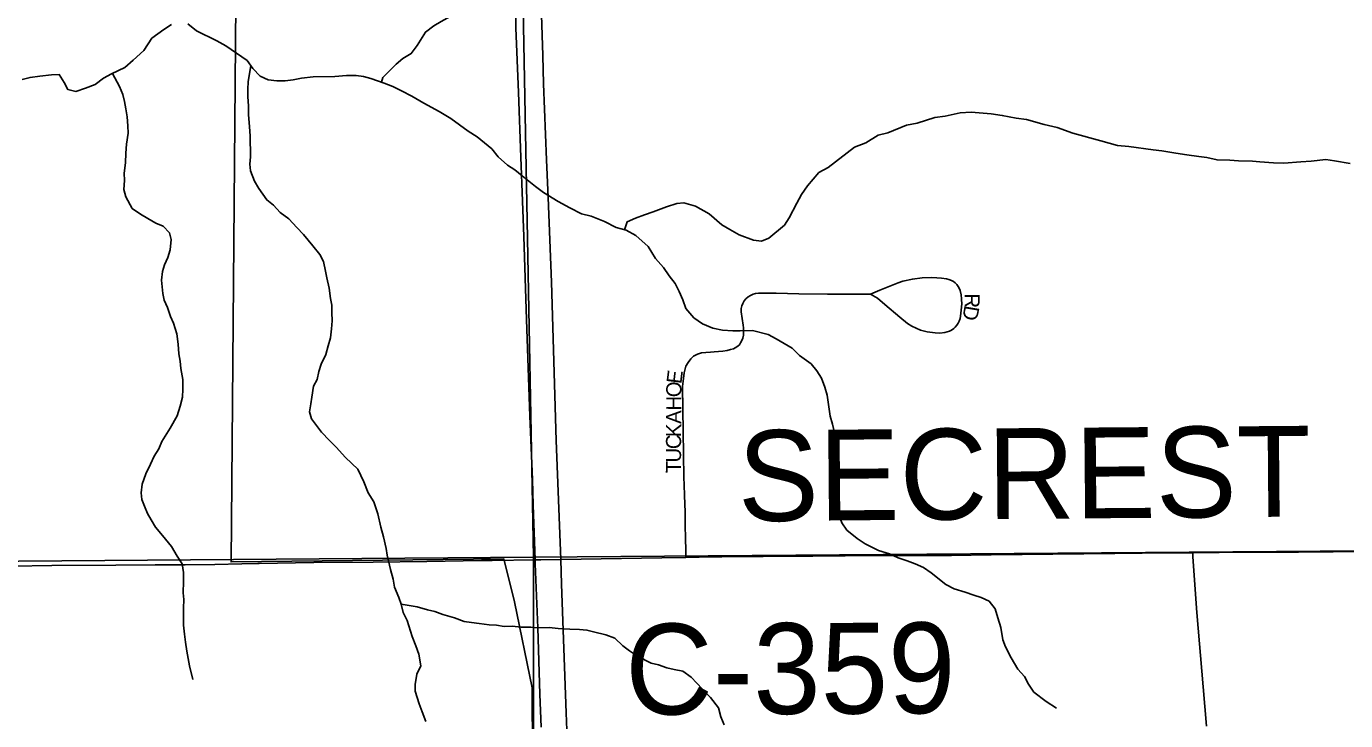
# Model space of a CAD drawing. Extents: x 1985906 to 2360102, y 891258 to 1222054.
# Drawn here: x 2128971 to 2133334, y 1014269 to 1016563 of the extents above; entities that cross this region are included whole.
import ezdxf

# ---------------------------------------------------------------- set-up
doc = ezdxf.new("R2010")
doc.units = 0
for name, color, linetype in [('GM_X_City_Street', 7, 'Continuous'), ('GM_X_Corporation', 7, 'Continuous'), ('GM_X_County_Road', 7, 'Continuous'), ('GM_X_County_Road_Text', 7, 'Continuous'), ('GM_X_Minor_River', 7, 'Continuous'), ('GM_X_Section', 7, 'Continuous'), ('GM_X_Township_Road', 7, 'Continuous'), ('GM_X_Township_Subdivision', 7, 'Continuous'), ('GM_X_Township_Subdivision_Text', 7, 'Continuous'), ('GM_X_US_Route', 7, 'Continuous')]:
    doc.layers.add(name, color=color, linetype=linetype)

msp = doc.modelspace()

# ---------------------------------------------------------------- linework, layer by layer
at = {"layer": 'GM_X_City_Street'}
msp.add_lwpolyline([(2128813.1, 1014778.2), (2128923.3, 1014779.7), (2129054.7, 1014781.3), (2129266.2, 1014783.1), (2129397.2, 1014783.8), (2129495.6, 1014784.2), (2129593.8, 1014784.9), (2129683.8, 1014786.7)], dxfattribs=at)
at = {"layer": 'GM_X_Corporation'}
msp.add_lwpolyline([(2129663.7, 1016638.8), (2129647.7, 1014793.7), (2130550, 1014803.2), (2130585.3, 1014661.5), (2130643.1, 1014377.4), (2130645.8, 1013927.4), (2130636.7, 1013870.1), (2130637.7, 1013720.1), (2130677.7, 1013567.2), (2130448.1, 1009980.8)], dxfattribs=at)
at = {"layer": 'GM_X_County_Road'}
for points in [[(2131151.7, 1014808.5), (2131195.8, 1014808.9), (2131270.8, 1014809.8), (2131367.2, 1014810.9), (2131407.8, 1014811.4), (2131473.5, 1014811.9), (2131510.5, 1014812.4), (2131571.4, 1014812.9), (2131620.4, 1014813.3), (2131678.7, 1014813.7), (2131733.5, 1014814.1), (2131785.6, 1014814.5), (2131866.9, 1014814.7), (2132030.3, 1014815), (2132161.7, 1014817), (2132570.8, 1014821.4), (2132751.2, 1014823.1), (2132827.9, 1014823.7)], [(2132827.9, 1014823.7), (2132915.4, 1014824.8), (2133178, 1014825.5), (2133407.8, 1014827.6), (2133736.1, 1014829.7), (2133998.6, 1014831.4), (2134230, 1014832.7), (2134392, 1014833.7), (2134533.6, 1014833.6)], [(2129683.8, 1014786.7), (2129736.5, 1014787.8)], [(2129736.5, 1014787.8), (2129740.7, 1014787.8), (2129922, 1014791.4), (2130117.8, 1014793.1), (2130295.5, 1014795), (2130475.5, 1014797.9), (2130511.6, 1014798.2)], [(2130511.6, 1014798.2), (2130653, 1014799.9), (2130672.2, 1014800.1), (2130738.1, 1014801.2), (2131072.4, 1014807.1)], [(2131072.4, 1014807.1), (2131151.7, 1014808.5)]]:
    msp.add_lwpolyline(points, dxfattribs=at)
at = {"layer": 'GM_X_Minor_River'}
for points in [[(2130144.9, 1016379.6), (2130150.1, 1016394.3), (2130193.7, 1016439), (2130215.5, 1016457.4), (2130243.4, 1016473.8), (2130263.2, 1016500.2), (2130290.7, 1016544.6), (2130318.5, 1016565.1), (2130342.5, 1016579.4), (2130420.2, 1016622.6), (2130454.1, 1016643.1), (2130477.9, 1016663.5), (2130503.8, 1016677.8), (2130535.6, 1016704.3), (2130569.4, 1016730.9), (2130597.2, 1016753.3), (2130648.9, 1016794.1), (2130672.8, 1016814.5), (2130712.7, 1016831), (2130734.7, 1016835.4), (2130764.8, 1016839.8), (2130786.7, 1016852.1), (2130824.2, 1016860.5)], [(2128957.3, 1016388.5), (2128983.3, 1016394.8), (2129015.4, 1016399.3), (2129053.5, 1016403.8), (2129079.6, 1016404.1), (2129096, 1016378.3), (2129108.4, 1016354.4), (2129134.5, 1016348.7), (2129166.5, 1016359.2), (2129198.5, 1016371.6), (2129226.4, 1016392.1), (2129252.3, 1016406.4), (2129296.2, 1016427.1), (2129324, 1016451.5), (2129359.7, 1016484.1), (2129385.3, 1016524.5), (2129425.1, 1016553.2), (2129451, 1016569.5)], [(2129505.2, 1016572.3), (2129533.6, 1016548.6), (2129600.3, 1016515.4), (2129630.6, 1016499.7), (2129701.5, 1016450.5), (2129719.9, 1016424.7), (2129744.4, 1016399), (2129770.6, 1016387.3), (2129798.8, 1016383.6), (2129826.9, 1016384)], [(2129712.9, 1016434.5), (2129704.4, 1016380.4), (2129702.7, 1016356.3), (2129703.1, 1016332.2), (2129705.5, 1016300.2), (2129705.8, 1016272.1), (2129708.4, 1016232), (2129710.8, 1016202), (2129711.7, 1016131.8), (2129710, 1016107.7), (2129712.3, 1016085.7), (2129724.8, 1016051.7), (2129739.1, 1016027.8), (2129765.7, 1015990.1), (2129788.1, 1015972.3), (2129810.5, 1015948.6), (2129838.8, 1015926.9), (2129865.3, 1015899.2), (2129887.7, 1015875.4), (2129918.3, 1015837.7), (2129940.8, 1015809.9), (2129953.1, 1015786), (2129959.6, 1015754), (2129963.9, 1015732), (2129972.4, 1015698), (2129976.8, 1015664), (2129981.1, 1015642), (2129981.4, 1015617.9), (2129981.8, 1015589.8), (2129980.1, 1015563.7), (2129976.5, 1015533.6), (2129968.8, 1015507.4), (2129961.1, 1015479.2), (2129945.5, 1015446.9), (2129937.8, 1015422.8), (2129932.1, 1015396.6), (2129920.3, 1015374.4), (2129914.8, 1015338.2), (2129911, 1015316.1), (2129907.4, 1015290), (2129913.7, 1015266), (2129946.4, 1015222.3), (2129972.9, 1015194.6), (2129995.2, 1015172.8), (2130025.8, 1015139.1), (2130066.5, 1015099.6), (2130087.1, 1015057.7), (2130101.6, 1015021.8), (2130120.1, 1014992), (2130132.6, 1014952), (2130143.3, 1014908.1), (2130151.7, 1014876.1), (2130160.2, 1014838.1), (2130164.5, 1014816.1), (2130175.2, 1014768.1), (2130183.6, 1014736.1), (2130188, 1014710.1), (2130202.5, 1014676.2), (2130210.8, 1014654.2), (2130217.2, 1014626.2), (2130229.6, 1014600.3), (2130246.4, 1014546.4), (2130258.8, 1014516.5), (2130269.2, 1014488.5), (2130275.7, 1014450.5), (2130262, 1014422.3), (2130256.4, 1014388.1), (2130256.7, 1014366), (2130269.3, 1014324.1), (2130279.7, 1014298.1), (2130292.2, 1014266.2)], [(2129255.3, 1016407.9), (2129278.9, 1016364.7), (2129289.3, 1016338.8), (2129295.6, 1016314.8), (2129300, 1016290.8), (2129304.3, 1016264.7), (2129306.7, 1016234.7), (2129307, 1016210.6), (2129301.5, 1016174.4), (2129299.8, 1016144.3), (2129298.3, 1016112.2), (2129294.7, 1016078.1), (2129295, 1016054), (2129293.4, 1016023.9), (2129299.7, 1015999.9), (2129320.3, 1015962.1), (2129348.7, 1015942.4), (2129372.9, 1015928.7), (2129399.2, 1015913), (2129423.5, 1015903.3), (2129443.8, 1015881.5), (2129450.1, 1015859.5), (2129446.6, 1015825.4), (2129438.9, 1015799.2), (2129427.1, 1015775), (2129421.4, 1015752.8), (2129417.8, 1015724.7), (2129422.3, 1015680.7), (2129426.6, 1015658.7), (2129437, 1015634.7), (2129447.4, 1015604.8), (2129457.8, 1015582.8), (2129468.3, 1015546.9), (2129472.7, 1015512.9), (2129475.1, 1015480.8), (2129479.5, 1015456.8), (2129481.8, 1015432.8), (2129488.3, 1015396.7), (2129488.7, 1015364.7), (2129487, 1015338.5), (2129479.4, 1015308.4), (2129469.8, 1015276.1), (2129446.2, 1015235.7), (2129418.7, 1015191.2), (2129408.9, 1015167), (2129393.2, 1015142.8), (2129381.5, 1015116.5), (2129365.8, 1015084.2), (2129354.2, 1015050), (2129350.6, 1015021.8), (2129352.9, 1014999.8), (2129361.2, 1014977.9), (2129371.5, 1014953.9), (2129383.9, 1014932), (2129398.2, 1014908.2), (2129420.7, 1014880.4), (2129451.3, 1014844.7), (2129469.8, 1014812.8), (2129486.2, 1014787), (2129490.5, 1014759), (2129490.9, 1014728.9), (2129489.4, 1014690.8), (2129491.7, 1014668.7), (2129490.1, 1014640.6), (2129490.8, 1014584.5), (2129493.2, 1014554.4), (2129497.5, 1014528.4), (2129501.9, 1014498.4), (2129510.6, 1014450.3), (2129521.2, 1014404.4)], [(2129826.9, 1016384), (2129853, 1016386.4), (2129881, 1016392.8), (2129919.1, 1016397.3), (2129991.4, 1016398.2), (2130029.5, 1016400.8), (2130061.6, 1016401.2), (2130085.8, 1016397.5), (2130109.9, 1016391.8), (2130154.3, 1016376.3), (2130182.6, 1016364.7), (2130210.9, 1016351), (2130245.2, 1016333.4), (2130285.7, 1016309.9), (2130336.3, 1016282.5), (2130374.7, 1016258.9), (2130431.5, 1016217.6), (2130461.9, 1016197.9), (2130510.6, 1016158.5), (2130531, 1016132.7), (2130561.5, 1016105), (2130585.8, 1016089.3), (2130610.1, 1016069.5), (2130654.8, 1016034), (2130681.1, 1016014.3), (2130729.7, 1015984.9), (2130768.1, 1015963.3), (2130806.5, 1015943.8), (2130838.8, 1015936.2), (2130883.2, 1015918.8), (2130921.6, 1015899.2), (2130953.9, 1015889.6), (2130986.2, 1015872), (2131026.8, 1015836.4), (2131051.5, 1015796.6), (2131077.9, 1015766.9), (2131096.4, 1015739.1), (2131116.8, 1015713.3), (2131129.2, 1015687.4), (2131141.6, 1015659.4), (2131152, 1015631.5), (2131178.5, 1015599.8), (2131206.9, 1015580.1), (2131241.2, 1015566.5), (2131273.4, 1015558.9), (2131307.6, 1015557.4), (2131331.7, 1015557.7), (2131371.8, 1015558.2), (2131424.2, 1015544.9), (2131450.5, 1015531.2), (2131503.1, 1015499.8), (2131527.5, 1015476.1), (2131566, 1015448.5), (2131584.4, 1015424.7), (2131600.8, 1015400.8), (2131611.2, 1015370.9), (2131619.6, 1015344.9), (2131628.5, 1015274.8), (2131636.9, 1015248.9), (2131647.6, 1015200.9), (2131648, 1015170.8), (2131652.7, 1015116.7), (2131651.4, 1015058.5), (2131652.4, 1014984.3), (2131656.8, 1014952.3), (2131667.2, 1014922.4), (2131683.6, 1014898.5), (2131718.1, 1014870.9), (2131744.4, 1014853.2), (2131788.9, 1014831.7), (2131825.2, 1014820.2), (2131853.5, 1014806.5), (2131883.7, 1014796.9), (2131910, 1014787.2), (2131938.2, 1014775.5), (2131962.6, 1014757.8), (2132011.3, 1014718.3), (2132039.6, 1014704.7), (2132075.9, 1014693.1), (2132104.1, 1014683.5), (2132128.3, 1014675.8), (2132154.5, 1014664.1), (2132175, 1014638.3), (2132183.4, 1014608.3), (2132193.8, 1014576.4), (2132200.4, 1014536.3), (2132208.7, 1014512.4), (2132227.3, 1014476.5), (2132249.8, 1014438.7), (2132272.2, 1014415), (2132284.6, 1014389), (2132303, 1014363.2), (2132343.6, 1014331.7), (2132378, 1014310.1)], [(2130948.7, 1015891.1), (2130957.5, 1015917.7), (2130985.5, 1015930.1), (2131015.4, 1015940.6), (2131043.4, 1015951), (2131087.4, 1015967.6), (2131121.4, 1015978.1), (2131145.5, 1015980.4), (2131183.8, 1015968.9), (2131228.3, 1015943.4), (2131270.9, 1015907.9), (2131297.2, 1015892.2), (2131327.6, 1015874.5), (2131376, 1015857.1), (2131402.1, 1015853.5), (2131426.1, 1015863.8), (2131477.8, 1015906.6), (2131493.5, 1015930.9), (2131519, 1015979.4), (2131534.7, 1016007.7), (2131554.4, 1016036), (2131592, 1016080.6), (2131621.9, 1016097.1), (2131709.4, 1016164.4), (2131747.3, 1016179), (2131787.2, 1016203.6), (2131819.2, 1016212), (2131881.1, 1016236.9), (2131917.2, 1016243.4), (2131975.2, 1016262.2), (2132009.3, 1016266.7), (2132059.3, 1016277.4), (2132095.4, 1016279.9), (2132161.8, 1016274.7), (2132198, 1016269.2), (2132244.3, 1016259.8), (2132278.5, 1016256.2), (2132336.9, 1016239), (2132379.2, 1016229.5), (2132431.7, 1016210.2), (2132524.4, 1016185.3), (2132578.8, 1016170), (2132617, 1016166.5), (2132697.5, 1016155.5), (2132725.6, 1016151.9), (2132771.9, 1016144.5), (2132808.1, 1016138.9), (2132848.4, 1016133.5), (2132874.5, 1016129.8), (2132908.8, 1016122.2), (2132951, 1016120.8), (2132979.1, 1016119.2), (2133025.3, 1016117.8), (2133049.4, 1016116.1), (2133095.6, 1016112.7), (2133129.8, 1016111.2), (2133186, 1016115.9), (2133220.1, 1016118.4), (2133268.2, 1016123), (2133296.4, 1016119.4), (2133348.7, 1016110.1)], [(2130210.8, 1014654.2), (2130263.1, 1014644.9), (2130297.4, 1014635.3), (2130321.6, 1014629.6), (2130347.8, 1014620), (2130386.1, 1014608.4), (2130418.4, 1014596.8), (2130442.5, 1014593.2), (2130468.7, 1014589.5), (2130500.9, 1014585.9), (2130525, 1014584.2), (2130551.1, 1014580.5), (2130577.2, 1014580.9), (2130607.4, 1014577.3), (2130639.5, 1014577.7), (2130661.6, 1014576), (2130699.8, 1014576.5), (2130730, 1014572.9), (2130768.1, 1014571.4), (2130800.3, 1014569.8), (2130824.4, 1014568.2), (2130846.6, 1014562.4), (2130886.9, 1014552.9), (2130917.1, 1014541.3), (2130943.6, 1014515.6), (2130965.9, 1014499.8), (2130992.2, 1014482.1), (2131036.7, 1014458.7), (2131060.9, 1014453), (2131089.1, 1014443.3), (2131113.3, 1014437.6), (2131141.5, 1014432), (2131169.8, 1014412.3), (2131206.5, 1014372.7), (2131233, 1014344.9), (2131259.5, 1014311.2), (2131267.9, 1014281.2), (2131278.3, 1014255.3)]]:
    msp.add_lwpolyline(points, dxfattribs=at)
at = {"layer": 'GM_X_Section'}
for points in [[(2130549.1, 1020075.3), (2130647.9, 1014808.7), (2125116.8, 1014766.3), (2125107.5, 1020101.4)], [(2135768, 1020137.7), (2135850.9, 1014849.1), (2130647.9, 1014808.7), (2130549.1, 1020075.3)], [(2130647.9, 1014808.7), (2135850.9, 1014849.1), (2135869.9, 1009550.1), (2130575.1, 1009477.1), (2130644.2, 1011228.6)], [(2125116.8, 1014766.3), (2130647.9, 1014808.7), (2130644.2, 1011228.6), (2130575.1, 1009477.1), (2125143.7, 1009493.4)]]:
    msp.add_lwpolyline(points, close=True, dxfattribs=at)
at = {"layer": 'GM_X_Township_Road'}
msp.add_lwpolyline([(2132873.1, 1014250.5), (2132862.4, 1014381.1), (2132841.4, 1014626.2), (2132828.8, 1014810.3), (2132827.9, 1014823.7)], dxfattribs=at)
at = {"layer": 'GM_X_Township_Subdivision'}
msp.add_lwpolyline([(2131151.7, 1014808.5), (2131151.5, 1014831.4), (2131150.7, 1014871.5), (2131150, 1014913.7), (2131149.5, 1014936.1), (2131149.1, 1014957.5), (2131147.4, 1015012.7), (2131146.3, 1015048.1), (2131145.5, 1015072.1), (2131143.9, 1015149.7), (2131142.4, 1015224.2), (2131140.9, 1015372.7), (2131143.5, 1015399.2), (2131146.1, 1015418.5), (2131151.9, 1015439.9), (2131159.2, 1015452.4), (2131168.5, 1015464.4), (2131177.4, 1015473.2), (2131190.4, 1015480.5), (2131204, 1015484.7), (2131217.5, 1015485.2), (2131233.1, 1015486.7), (2131245.1, 1015488.3), (2131259.7, 1015488.8), (2131273.8, 1015490.4), (2131288.9, 1015492.5), (2131299.8, 1015495.1), (2131309.2, 1015498.2), (2131320.1, 1015503.9), (2131328.7, 1015511.2), (2131333, 1015517.6), (2131337, 1015524.8), (2131339.8, 1015532.7), (2131342, 1015542.5), (2131342.7, 1015549.1), (2131342.9, 1015559.3), (2131342.4, 1015567.1), (2131341.1, 1015575.6), (2131334.5, 1015619.5), (2131334.8, 1015631.3), (2131337, 1015640.1), (2131340.5, 1015647.6), (2131344.9, 1015656.4), (2131350.2, 1015663.3), (2131357.4, 1015669.3), (2131365.3, 1015674), (2131374.6, 1015678.3), (2131382.5, 1015680.8), (2131391.6, 1015681.8), (2131450.2, 1015681.5), (2131525.7, 1015680), (2131620.5, 1015678.6), (2131762.2, 1015678.9), (2131792.9, 1015691.4), (2131853.5, 1015716), (2131869, 1015721.2), (2131900.8, 1015728.4), (2131933, 1015732.1), (2131965.3, 1015733.2), (2131981.3, 1015732.6), (2131997.5, 1015731.5), (2132014.1, 1015729.1), (2132021.9, 1015727), (2132029.8, 1015724), (2132037, 1015719.8), (2132042.4, 1015716.1), (2132047.8, 1015710.4), (2132052.7, 1015704.1), (2132055.7, 1015698.3), (2132058.7, 1015690.6), (2132062.3, 1015676.2), (2132063.7, 1015662.9), (2132063.8, 1015659.6), (2132064.2, 1015648), (2132063.8, 1015635), (2132060.1, 1015605.7), (2132058.7, 1015598.1), (2132055.9, 1015589.6), (2132052.4, 1015582.4), (2132048.1, 1015576), (2132042.8, 1015569.8), (2132037.6, 1015565.2), (2132030.3, 1015559.9), (2132023.4, 1015556.4), (2132015.8, 1015553.6), (2132008.1, 1015551.6), (2131992, 1015549.9), (2131975.7, 1015550.8), (2131949.8, 1015554.3), (2131928.2, 1015559.7), (2131913.3, 1015565.7), (2131898.7, 1015573), (2131885, 1015581.9), (2131859.4, 1015602.1), (2131810.3, 1015644.6), (2131785.9, 1015665), (2131762.2, 1015678.9)], dxfattribs=at)
at = {"layer": 'GM_X_US_Route'}
for points in [[(2130588.9, 1016672.2), (2130589.7, 1016558.2), (2130597.8, 1016345.2), (2130606.4, 1016131.1), (2130611.4, 1015986.1), (2130615.7, 1015868.9), (2130624.6, 1015594.2), (2130636.3, 1015275.4), (2130644.8, 1015066.3), (2130647.1, 1014981.1), (2130653, 1014799.9), (2130653.4, 1014787.3), (2130662.7, 1014575.1), (2130668.9, 1014356.3), (2130673.1, 1014247.3)], [(2130672.2, 1016670.3), (2130678.8, 1016467.3), (2130681, 1016373.8), (2130690.9, 1016122.7), (2130695.9, 1015997.7), (2130706.9, 1015718.4), (2130723.4, 1015195.1), (2130738.1, 1014801.2), (2130740.9, 1014720.4), (2130756, 1014294.6), (2130760.4, 1014179.9), (2130778.3, 1013704.9), (2130787.1, 1013442.9), (2130805.2, 1012918.7), (2130815.5, 1012607.5), (2130823.9, 1012378.3), (2130834.5, 1012067.2), (2130849.2, 1011690.6), (2130849.4, 1011682.6), (2130854.7, 1011526.8), (2130858.9, 1011412.1), (2130863.8, 1011269.9), (2130869.9, 1011088.4)]]:
    msp.add_lwpolyline(points, dxfattribs=at)

# ---------------------------------------------------------------- texts
at = {"layer": 'GM_X_County_Road_Text'}
for s, rotation, p in [('SECREST', 0.4761, (2131324.7, 1014927.8)), ('C-359', 0.2728, (2130951.7, 1014288.5))]:
    msp.add_text(s, height=300, rotation=rotation, dxfattribs=at).set_placement(p)
at = {"layer": 'GM_X_Township_Subdivision_Text'}
for s, rotation, p in [('R', 269.4171, (2132073.9, 1015681.1)), ('D', 260.4478, (2132073.7, 1015643.5)), ('O', 89.694, (2131136.8, 1015337.7)), ('E', 83.0715, (2131136.9, 1015380.1)), ('H', 89.6887, (2131136.6, 1015293.7)), ('A', 89.694, (2131136.3, 1015249.7)), ('C', 89.6843, (2131135.9, 1015166)), ('K', 89.7057, (2131136.1, 1015205.7)), ('T', 89.6994, (2131135.5, 1015086.8)), ('U', 89.694, (2131135.7, 1015122))]:
    msp.add_text(s, height=50, rotation=rotation, dxfattribs=at).set_placement(p)

doc.saveas('drawing.dxf')
